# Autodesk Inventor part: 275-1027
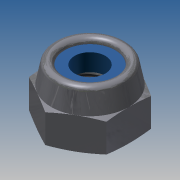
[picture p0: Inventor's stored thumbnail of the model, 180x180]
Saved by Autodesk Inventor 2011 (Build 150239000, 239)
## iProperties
Shininess: 60.0
Company: Autodesk Inc.
Created: 2010-06
Part Number: 275-1027
Document SubType Name: Modeling
Designer: Autodesk Inc.
Description: Nylock Nut
Material: Steel, Mild
Density: 7.86 g/cm^3
Catalog Web Link: http://www.vexrobotics.com/nuts-8-32.html
Vendor: Innovation First, Inc.
Density: 7.859999999999999
Volumn: 40.07686313737254
Area: 115.62685411210367
PropertySet Name: Model Information
Control State: 0
Master: False
Checked Out: False
Title: VEX Robotics Kit of Parts
Author: Autodesk Inc.
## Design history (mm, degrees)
sketch "Sketch2"
  geometry: L1 (1.498, 7.147)-(5.864, 4.626); L2 (5.864, 4.626)-(5.864, -0.416); L3 (5.864, -0.416)-(1.498, -2.937); L4 (1.498, -2.937)-(-2.868, -0.416); L5 (-2.868, -0.416)-(-2.868, 4.626); L6 (-2.868, 4.626)-(1.498, 7.147); C1 r 4.366 at (1.498, 2.105); 1 further point
  constraints: 12 end point, 5 tangent, 3 equal length, 3 parallel, 1 centre point, 1 coincident, 1 vertical
  dimensions: "d0" = 8.73252 diameter of C1 (derived)
feature "Hexagon_flats_join1" sketch "Sketch2"
sketch "Sketch3"
  geometry: C1 r 2.083 at (4.366, 2.521); 1 further point
  constraints: 1 centre point, 1 coincident
  dimensions: "nut_id" = 4.1656 diameter of C1
extrude "Extrusion1" cut sketch "Sketch3" stored distance "d3" = 25.4; taper "d4" = 0 deg
sketch "Sketch1"
  geometry: L1 (4.366, 0)-(4.366, 3.556) reference; L2 (-2.083, 3.556)-(2.083, 3.556) reference; L3 (4.366, 3.556)-(3.967, 5.612); L4 (2.844, 5.504)-(2.844, 3.556); L5 (4.366, 3.556)-(2.844, 3.556); L6 (-0.396, 6.071)-(7.419, 6.071); L7 (0, -2.386)-(0, 14.317) reference; A1 r 0.567 centre (3.41, 5.504) between (3.967, 5.612) and (2.844, 5.504)
  constraints: 8 end point, 3 tangent, 2 horizontal, 2 point on circle, 1 centre point, 1 vertical
  dimensions: "d5" = 79 deg angle of L5 L3; "nut_height" = 6.0706 distance from line of L6 L1.start; "d11" = 1.52231 distance of L1.end L4.end (= -0.333333 x nut_id + 0.333333 x hex_size)
revolve "Revolution1" sketch "Sketch1" stored, may be unused: angle "d7" = 90 deg
workplane "Work Plane1"
sketch "Sketch4"
  geometry: C1 r 2.083 at (2.844, 0) reference; C2 r 1.727 at (2.844, 0); C3 r 2.844 at (2.844, 0) reference
  constraints: 1 centre point, 1 coincident
  dimensions: "nylon_id" = 3.4544 diameter of C2
extrude "Extrusion2" join sketch "Sketch4" stored distance "d9" = 25.4; taper "d10" = 0 deg
sketch "Sketch5"
  geometry: L1 (-1.646, 0)-(9.876, 0) reference; L2 (0, -2.521)-(0, -5.042) reference; L3 (3.556, -5.042)-(3.556, -3.781) reference; L4 (0, -5.042)-(3.556, -5.042); L5 (3.556, -4.366)-(3.375, -5.042); L6 (0.181, -5.042)-(0, -4.366)
  constraints: 6 end point, 4 point on line, 1 horizontal, 1 horizontal alignment
  dimensions: "d12" = 15 deg angle of L2 L6; "d13" = 15 deg angle of L3 L5 (= d12); "d14" = 8.73252 diameter of L6.end L1 (= hex_size)
revolve "Revolution2" sketch "Sketch5" stored, may be unused: angle "d15" = 90 deg
thread "Thread1" dims "d16" = 25.4, "d17" = 0
body "Solid1"
other parameters: "hex_size" = 8.73252 [user parameter; used in 3 equation terms], "hex_height" = 3.556 [user parameter; used in 1 equation term]
